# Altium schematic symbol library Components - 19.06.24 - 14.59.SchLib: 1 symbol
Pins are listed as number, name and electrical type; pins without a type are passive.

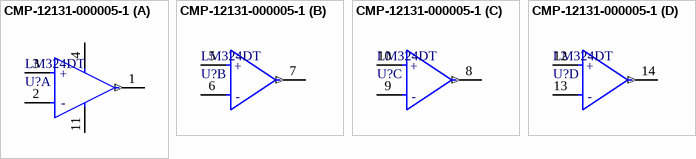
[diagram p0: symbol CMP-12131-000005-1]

## CMP-12131-000005-1
designator U?, comment LM324DT
IC OPAMP GP 4 CIRCUIT 14SO; Manufacturer: STMicroelectronics; Voltage Gain: 100dB; Standoff Height: 0.1mm; Bandwidth: 1.3MHz; Max Junction Temp: +150°C; Min Supply Voltage: 3V; Max Dual Supply Voltage: 15V; Min Dual Supply Voltage: 1.5V; Number Of Channels: 4; Nominal Supply Current: 0.7-1.5mA; Output Current Per Channel: 20-50mA; Max Supply Voltage: 30V; Input Offset Voltage: 2mV; Input Bias Current: 0.02uA
footprint FP-SO-14-IPC_C
footprint FP-SO-14-MFG
footprint FP-SO-14-IPC_B
footprint FP-SO-14-IPC_A
part A pins: 1 Output 1 (out), 2 Inverting Input 1 (hiz), 3 Non-Inverting Input 1 (hiz), 4 VCC+ (power), 11 VCC- (power)
part B pins: 5 Non-Inverting Input 2 (hiz), 6 Inverting Input 2 (hiz), 7 Output 2 (out)
part C pins: 8 Output 3 (out), 9 Inverting Input 3 (hiz), 10 Non-Inverting Input 3 (hiz)
part D pins: 12 Non-Inverting Input 4 (hiz), 13 Inverting Input 4 (hiz), 14 Output 4 (out)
